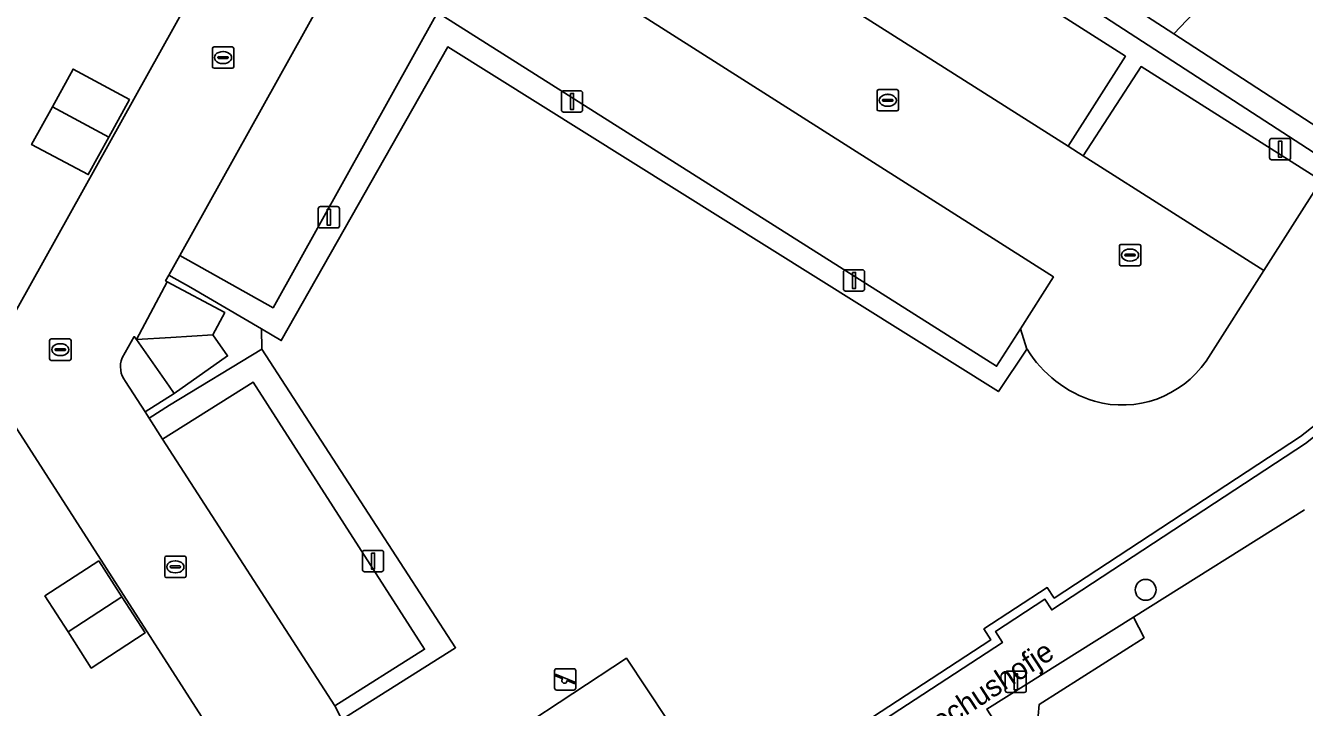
# Model space of a CAD drawing. Extents: x 161798 to 162385, y 382315 to 382833.
# Drawn here: x 162038.7 to 162098.6, y 382627.8 to 382659.8 of the extents above; entities that cross this region are included whole.
import ezdxf

# ---------------------------------------------------------------- set-up
doc = ezdxf.new("R2010")
doc.units = 0
for name, color, linetype in [('IMGEO_Boom', 7, 'Continuous'), ('IMGEO_Erf', 7, 'Continuous'), ('IMGEO_Grasland_overig', 7, 'Continuous'), ('IMGEO_Groenvoorziening', 7, 'Continuous'), ('IMGEO_Haag', 7, 'Continuous'), ('IMGEO_Kolk', 7, 'Continuous'), ('IMGEO_Lichtmast', 7, 'Continuous'), ('IMGEO_Openbare_ruimte_label', 7, 'Continuous'), ('IMGEO_Pand', 7, 'Continuous'), ('IMGEO_Parkeervlak_open', 7, 'Continuous'), ('IMGEO_Rijbaan_lokaal_open', 7, 'Continuous'), ('IMGEO_Speelvoorziening', 7, 'Continuous'), ('IMGEO_Voetpad_halfverhard', 7, 'Continuous'), ('IMGEO_Voetpad_open', 7, 'Continuous')]:
    doc.layers.add(name, color=color, linetype=linetype)

msp = doc.modelspace()

# ---------------------------------------------------------------- linework, layer by layer
at = {"layer": 'IMGEO_Boom'}
msp.add_circle((162091.193, 382633.351), 0.489, dxfattribs=at)
at = {"layer": 'IMGEO_Erf'}
for points in [[(162037.089, 382644.31), (162054.299, 382675.209)], [(162038.559, 382617.282), (162041.785, 382619.378), (162042.883, 382620.082), (162044.823, 382621.326), (162043.353, 382623.574), (162047.566, 382626.266), (162049.021, 382623.989), (162049.126, 382624.056), (162037.386, 382642.326)], [(162098.642, 382637.101), (162090.621, 382632.077), (162091.121, 382631.109), (162086.211, 382627.989), (162086.065, 382626.396), (162085.935, 382626.314), (162096.136, 382610.823), (162098.869, 382612.622), (162093.624, 382620.587), (162096.461, 382622.456), (162096.703, 382622.616), (162099.695, 382624.586)]]:
    msp.add_lwpolyline(points, dxfattribs=at)
for points in [[(162039.979, 382655.972), (162040.95, 382657.742), (162043.593, 382656.309), (162042.628, 382654.553), (162041.663, 382652.796), (162039.008, 382654.202)], [(162042.153, 382634.71), (162043.237, 382633.023), (162044.321, 382631.337), (162041.799, 382629.691), (162040.715, 382631.378), (162039.631, 382633.064)]]:
    msp.add_lwpolyline(points, close=True, dxfattribs=at)
at = {"layer": 'IMGEO_Grasland_overig'}
for points in [[(162100.721, 382642.321), (162098.453, 382640.526), (162086.912, 382632.968), (162086.587, 382633.461), (162083.617, 382631.522), (162083.938, 382631.006), (162071.632, 382622.978), (162071.854, 382622.645), (162084.484, 382630.885), (162084.164, 382631.401), (162086.472, 382632.908), (162086.798, 382632.415), (162098.687, 382640.201), (162100.953, 382641.994), (162107.365, 382646.048), (162107.093, 382646.349)], [(162049.39, 382643.077), (162057.419, 382630.57), (162053.217, 382627.917), (162053.546, 382627.275), (162058.865, 382630.636), (162049.788, 382644.621), (162045.462, 382642.006), (162044.511, 382641.395), (162045.145, 382640.409)]]:
    msp.add_lwpolyline(points, close=True, dxfattribs=at)
at = {"layer": 'IMGEO_Groenvoorziening'}
for points in [[(162085.636, 382644.628), (162084.298, 382642.637), (162058.5, 382658.78), (162050.703, 382645.029), (162049.772, 382645.572), (162049.788, 382644.621), (162058.865, 382630.636), (162053.546, 382627.275), (162060.874, 382615.465), (162063.849, 382617.311), (162065.587, 382618.465), (162065.303, 382618.88), (162066.568, 382619.672), (162061.847, 382626.837), (162066.874, 382630.15), (162071.632, 382622.978), (162083.938, 382631.006), (162083.617, 382631.522), (162086.587, 382633.461), (162086.912, 382632.968), (162098.453, 382640.526)], [(162098.453, 382640.526), (162100.721, 382642.321), (162107.093, 382646.349), (162105.404, 382648.013), (162101.431, 382651.203), (162099.476, 382652.633), (162099.415, 382652.521), (162096.732, 382648.306), (162094.025, 382644.065)]]:
    msp.add_lwpolyline(points, dxfattribs=at)
msp.add_lwpolyline([(162086.211, 382627.989), (162091.121, 382631.109), (162090.621, 382632.077), (162083.747, 382627.769), (162085.049, 382625.755), (162085.935, 382626.314), (162086.065, 382626.396)], close=True, dxfattribs=at)
for centre, radius, start, end in [((162090.469, 382647.611), 5.679, 211.68946, 252.87253), ((162090.091, 382646.793), 4.787, 254.30632, 325.2635)]:
    msp.add_arc(centre, radius, start, end, dxfattribs=at)
at = {"layer": 'IMGEO_Haag'}
msp.add_lwpolyline([(162098.687, 382640.201), (162100.953, 382641.994), (162107.365, 382646.048), (162107.093, 382646.349), (162100.721, 382642.321), (162098.453, 382640.526), (162086.912, 382632.968), (162086.587, 382633.461), (162083.617, 382631.522), (162083.938, 382631.006), (162071.632, 382622.978), (162071.854, 382622.645), (162084.484, 382630.885), (162084.164, 382631.401), (162086.472, 382632.908), (162086.798, 382632.415)], close=True, dxfattribs=at)
at = {"layer": 'IMGEO_Kolk'}
for p, q in [((162047.477, 382657.853), (162047.477, 382658.705)), ((162047.552, 382658.779), (162048.404, 382658.779)), ((162047.965, 382658.559), (162047.99, 382658.559)), ((162048.478, 382658.705), (162048.478, 382657.853)), ((162048.404, 382657.779), (162047.552, 382657.779)), ((162047.736, 382658.273), (162047.736, 382658.285)), ((162048.174, 382658.236), (162047.776, 382658.236)), ((162047.779, 382658.322), (162048.177, 382658.322)), ((162047.988, 382657.999), (162047.963, 382657.999)), ((162048.22, 382658.285), (162048.22, 382658.273)), ((162078.614, 382655.852), (162078.614, 382656.704)), ((162078.689, 382656.778), (162079.541, 382656.778)), ((162079.615, 382656.704), (162079.615, 382655.852)), ((162078.873, 382656.272), (162078.873, 382656.284)), ((162079.311, 382656.235), (162078.913, 382656.235)), ((162078.916, 382656.321), (162079.314, 382656.321)), ((162079.125, 382655.998), (162079.1, 382655.998)), ((162079.102, 382656.558), (162079.127, 382656.558)), ((162079.357, 382656.284), (162079.357, 382656.272)), ((162079.541, 382655.778), (162078.689, 382655.778)), ((162089.964, 382648.604), (162089.964, 382649.456)), ((162090.039, 382649.53), (162090.891, 382649.53)), ((162090.965, 382649.456), (162090.965, 382648.604)), ((162090.223, 382649.024), (162090.223, 382649.036)), ((162090.661, 382648.987), (162090.263, 382648.987)), ((162090.266, 382649.073), (162090.664, 382649.073)), ((162090.452, 382649.31), (162090.477, 382649.31)), ((162090.707, 382649.036), (162090.707, 382649.024)), ((162090.891, 382648.53), (162090.039, 382648.53)), ((162090.475, 382648.75), (162090.45, 382648.75)), ((162039.852, 382644.174), (162039.852, 382645.026)), ((162039.927, 382645.1), (162040.779, 382645.1)), ((162040.111, 382644.594), (162040.111, 382644.606)), ((162040.154, 382644.643), (162040.552, 382644.643)), ((162040.34, 382644.88), (162040.365, 382644.88)), ((162040.595, 382644.606), (162040.595, 382644.594)), ((162040.853, 382645.026), (162040.853, 382644.174)), ((162040.779, 382644.1), (162039.927, 382644.1)), ((162040.549, 382644.557), (162040.151, 382644.557)), ((162040.363, 382644.32), (162040.338, 382644.32)), ((162045.243, 382634.002), (162045.243, 382634.854)), ((162045.318, 382634.928), (162046.17, 382634.928)), ((162045.502, 382634.422), (162045.502, 382634.434)), ((162045.545, 382634.471), (162045.943, 382634.471)), ((162045.731, 382634.708), (162045.756, 382634.708)), ((162045.986, 382634.434), (162045.986, 382634.422)), ((162046.244, 382634.854), (162046.244, 382634.002)), ((162046.17, 382633.928), (162045.318, 382633.928)), ((162045.94, 382634.385), (162045.542, 382634.385)), ((162045.754, 382634.148), (162045.729, 382634.148))]:
    msp.add_line(p, q, dxfattribs=at)
for points in [[(162047.477, 382657.853), (162047.477, 382658.705)], [(162047.552, 382658.779), (162048.404, 382658.779)], [(162048.478, 382658.705), (162048.478, 382657.853)], [(162048.404, 382657.779), (162047.552, 382657.779)], [(162078.614, 382655.852), (162078.614, 382656.704)], [(162078.689, 382656.778), (162079.541, 382656.778)], [(162079.615, 382656.704), (162079.615, 382655.852)], [(162079.541, 382655.778), (162078.689, 382655.778)], [(162089.964, 382648.604), (162089.964, 382649.456)], [(162090.039, 382649.53), (162090.891, 382649.53)], [(162090.965, 382649.456), (162090.965, 382648.604)], [(162090.891, 382648.53), (162090.039, 382648.53)], [(162039.852, 382644.174), (162039.852, 382645.026)], [(162039.927, 382645.1), (162040.779, 382645.1)], [(162040.853, 382645.026), (162040.853, 382644.174)], [(162040.779, 382644.1), (162039.927, 382644.1)], [(162045.243, 382634.002), (162045.243, 382634.854)], [(162045.318, 382634.928), (162046.17, 382634.928)], [(162046.244, 382634.854), (162046.244, 382634.002)], [(162046.17, 382633.928), (162045.318, 382633.928)]]:
    msp.add_lwpolyline(points, dxfattribs=at)
for centre, radius, start, end in [((162047.554, 382658.703), 0.0765, 91.55205, 178.44795), ((162047.554, 382658.703), 0.0765, 91.55205, 178.44795), ((162048.402, 382658.703), 0.0765, 1.55205, 88.44795), ((162048.402, 382658.703), 0.0765, 1.55205, 88.44795), ((162047.554, 382657.855), 0.0765, 181.55205, 268.44795), ((162047.554, 382657.855), 0.0765, 181.55205, 268.44795), ((162047.776, 382658.282), 0.0403, 85.87752, 175.75265), ((162047.773, 382658.272), 0.0366, 178.93798, 274.71019), ((162048.177, 382658.279), 0.043, 264.86636, 352.45326), ((162048.181, 382658.284), 0.0386, 1.73085, 96.63898), ((162048.402, 382657.855), 0.0765, 271.55205, 358.44795), ((162048.402, 382657.855), 0.0765, 271.55205, 358.44795), ((162078.691, 382656.702), 0.0765, 91.55205, 178.44795), ((162078.691, 382656.702), 0.0765, 91.55205, 178.44795), ((162079.539, 382656.702), 0.0765, 1.55205, 88.44795), ((162079.539, 382656.702), 0.0765, 1.55205, 88.44795), ((162078.913, 382656.281), 0.0403, 85.87752, 175.75265), ((162078.91, 382656.271), 0.0366, 178.93798, 274.71019), ((162079.314, 382656.278), 0.043, 264.86636, 352.45326), ((162079.318, 382656.283), 0.0386, 1.73085, 96.63898), ((162078.691, 382655.854), 0.0765, 181.55205, 268.44795), ((162078.691, 382655.854), 0.0765, 181.55205, 268.44795), ((162079.539, 382655.854), 0.0765, 271.55205, 358.44795), ((162079.539, 382655.854), 0.0765, 271.55205, 358.44795), ((162090.041, 382649.454), 0.0765, 91.55205, 178.44795), ((162090.041, 382649.454), 0.0765, 91.55205, 178.44795), ((162090.889, 382649.454), 0.0765, 1.55205, 88.44795), ((162090.889, 382649.454), 0.0765, 1.55205, 88.44795), ((162090.263, 382649.033), 0.0403, 85.87752, 175.75265), ((162090.26, 382649.023), 0.0366, 178.93798, 274.71019), ((162090.664, 382649.03), 0.043, 264.86636, 352.45326), ((162090.668, 382649.035), 0.0386, 1.73085, 96.63898), ((162090.041, 382648.606), 0.0765, 181.55205, 268.44795), ((162090.041, 382648.606), 0.0765, 181.55205, 268.44795), ((162090.889, 382648.606), 0.0765, 271.55205, 358.44795), ((162090.889, 382648.606), 0.0765, 271.55205, 358.44795), ((162039.929, 382645.024), 0.0765, 91.55205, 178.44795), ((162039.929, 382645.024), 0.0765, 91.55205, 178.44795), ((162040.151, 382644.603), 0.0403, 85.87752, 175.75265), ((162040.148, 382644.593), 0.0366, 178.93798, 274.71019), ((162040.552, 382644.6), 0.043, 264.86636, 352.45326), ((162040.556, 382644.605), 0.0386, 1.73085, 96.63898), ((162040.777, 382645.024), 0.0765, 1.55205, 88.44795), ((162040.777, 382645.024), 0.0765, 1.55205, 88.44795), ((162039.929, 382644.176), 0.0765, 181.55205, 268.44795), ((162039.929, 382644.176), 0.0765, 181.55205, 268.44795), ((162040.777, 382644.176), 0.0765, 271.55205, 358.44795), ((162040.777, 382644.176), 0.0765, 271.55205, 358.44795), ((162045.32, 382634.852), 0.0765, 91.55205, 178.44795), ((162045.32, 382634.852), 0.0765, 91.55205, 178.44795), ((162045.542, 382634.431), 0.0403, 85.87752, 175.75265), ((162045.539, 382634.421), 0.0366, 178.93798, 274.71019), ((162045.943, 382634.428), 0.043, 264.86636, 352.45326), ((162045.947, 382634.433), 0.0386, 1.73085, 96.63898), ((162046.168, 382634.852), 0.0765, 1.55205, 88.44795), ((162046.168, 382634.852), 0.0765, 1.55205, 88.44795), ((162045.32, 382634.004), 0.0765, 181.55205, 268.44795), ((162045.32, 382634.004), 0.0765, 181.55205, 268.44795), ((162046.168, 382634.004), 0.0765, 271.55205, 358.44795), ((162046.168, 382634.004), 0.0765, 271.55205, 358.44795)]:
    msp.add_arc(centre, radius, start, end, dxfattribs=at)
for centre, major_axis, ratio, start_param, end_param in [((162047.964, 382658.279), (-0.387, 0.002), 0.722429, 4.712389, 7.853982), ((162047.989, 382658.279), (-0.39, 0.002), 0.717154, 1.570796, 4.712389), ((162079.101, 382656.278), (-0.387, 0.002), 0.722429, 4.712389, 7.853982), ((162079.126, 382656.278), (-0.39, 0.002), 0.717154, 1.570796, 4.712389), ((162090.451, 382649.03), (-0.387, 0.002), 0.722429, 4.712389, 7.853982), ((162090.476, 382649.03), (-0.39, 0.002), 0.717154, 1.570796, 4.712389), ((162040.339, 382644.6), (-0.387, 0.002), 0.722429, 4.712389, 7.853982), ((162040.364, 382644.6), (-0.39, 0.002), 0.717154, 1.570796, 4.712389), ((162045.73, 382634.428), (-0.387, 0.002), 0.722429, 4.712389, 7.853982), ((162045.755, 382634.428), (-0.39, 0.002), 0.717154, 1.570796, 4.712389)]:
    msp.add_ellipse(centre, major_axis=major_axis, ratio=ratio, start_param=start_param, end_param=end_param, dxfattribs=at)
at = {"layer": 'IMGEO_Lichtmast'}
for p, q in [((162063.829, 382655.827), (162063.829, 382656.627)), ((162063.829, 382656.627), (162063.829, 382655.827)), ((162063.929, 382656.727), (162064.719, 382656.727)), ((162064.719, 382656.727), (162063.929, 382656.727)), ((162064.819, 382656.627), (162064.819, 382655.827)), ((162064.819, 382655.827), (162064.819, 382656.627)), ((162064.719, 382655.727), (162063.929, 382655.727)), ((162063.929, 382655.727), (162064.719, 382655.727)), ((162096.997, 382653.591), (162096.997, 382654.391)), ((162096.997, 382654.391), (162096.997, 382653.591)), ((162097.097, 382654.491), (162097.887, 382654.491)), ((162097.887, 382654.491), (162097.097, 382654.491)), ((162097.987, 382654.391), (162097.987, 382653.591)), ((162097.987, 382653.591), (162097.987, 382654.391)), ((162097.887, 382653.491), (162097.097, 382653.491)), ((162097.097, 382653.491), (162097.887, 382653.491)), ((162052.435, 382650.399), (162052.435, 382651.199)), ((162052.435, 382651.199), (162052.435, 382650.399)), ((162052.535, 382651.299), (162053.325, 382651.299)), ((162053.325, 382651.299), (162052.535, 382651.299)), ((162053.425, 382651.199), (162053.425, 382650.399)), ((162053.425, 382650.399), (162053.425, 382651.199)), ((162053.325, 382650.299), (162052.535, 382650.299)), ((162052.535, 382650.299), (162053.325, 382650.299)), ((162077.037, 382647.444), (162077.037, 382648.244)), ((162077.037, 382648.244), (162077.037, 382647.444)), ((162077.137, 382648.344), (162077.927, 382648.344)), ((162077.927, 382648.344), (162077.137, 382648.344)), ((162078.027, 382648.244), (162078.027, 382647.444)), ((162078.027, 382647.444), (162078.027, 382648.244)), ((162077.927, 382647.344), (162077.137, 382647.344)), ((162077.137, 382647.344), (162077.927, 382647.344)), ((162054.504, 382634.301), (162054.504, 382635.101)), ((162054.504, 382635.101), (162054.504, 382634.301)), ((162054.604, 382635.201), (162055.394, 382635.201)), ((162055.394, 382635.201), (162054.604, 382635.201)), ((162055.494, 382635.101), (162055.494, 382634.301)), ((162055.494, 382634.301), (162055.494, 382635.101)), ((162055.394, 382634.201), (162054.604, 382634.201)), ((162054.604, 382634.201), (162055.394, 382634.201)), ((162084.615, 382628.645), (162084.615, 382629.445)), ((162084.615, 382629.445), (162084.615, 382628.645)), ((162084.715, 382629.545), (162085.505, 382629.545)), ((162085.505, 382629.545), (162084.715, 382629.545)), ((162085.605, 382629.445), (162085.605, 382628.645)), ((162085.605, 382628.645), (162085.605, 382629.445)), ((162085.505, 382628.545), (162084.715, 382628.545)), ((162084.715, 382628.545), (162085.505, 382628.545))]:
    msp.add_line(p, q, dxfattribs=at)
for points in [[(162064.249, 382656.602), (162064.399, 382656.602), (162064.399, 382655.852), (162064.249, 382655.852), (162064.249, 382656.602)], [(162097.417, 382654.366), (162097.567, 382654.366), (162097.567, 382653.616), (162097.417, 382653.616), (162097.417, 382654.366)], [(162052.855, 382651.174), (162053.005, 382651.174), (162053.005, 382650.424), (162052.855, 382650.424), (162052.855, 382651.174)], [(162077.457, 382648.219), (162077.607, 382648.219), (162077.607, 382647.469), (162077.457, 382647.469), (162077.457, 382648.219)], [(162054.924, 382635.076), (162055.074, 382635.076), (162055.074, 382634.326), (162054.924, 382634.326), (162054.924, 382635.076)], [(162085.035, 382629.42), (162085.185, 382629.42), (162085.185, 382628.67), (162085.035, 382628.67), (162085.035, 382629.42)]]:
    msp.add_lwpolyline(points, dxfattribs=at)
for centre, start, end in [((162063.929, 382656.627), 90, 180), ((162063.929, 382656.627), 90, 180), ((162064.719, 382656.627), 0, 90), ((162064.719, 382656.627), 360, 90), ((162063.929, 382655.827), 180, 270), ((162063.929, 382655.827), 180, 270), ((162064.719, 382655.827), 270, 0), ((162064.719, 382655.827), 270, 0), ((162097.097, 382654.391), 90, 180), ((162097.097, 382654.391), 90, 180), ((162097.887, 382654.391), 0, 90), ((162097.887, 382654.391), 360, 90), ((162097.097, 382653.591), 180, 270), ((162097.097, 382653.591), 180, 270), ((162097.887, 382653.591), 270, 0), ((162097.887, 382653.591), 270, 0), ((162052.535, 382651.199), 90, 180), ((162052.535, 382651.199), 90, 180), ((162053.325, 382651.199), 0, 90), ((162053.325, 382651.199), 360, 90), ((162052.535, 382650.399), 180, 270), ((162052.535, 382650.399), 180, 270), ((162053.325, 382650.399), 270, 0), ((162053.325, 382650.399), 270, 0), ((162077.137, 382648.244), 90, 180), ((162077.137, 382648.244), 90, 180), ((162077.927, 382648.244), 0, 90), ((162077.927, 382648.244), 360, 90), ((162077.137, 382647.444), 180, 270), ((162077.137, 382647.444), 180, 270), ((162077.927, 382647.444), 270, 0), ((162077.927, 382647.444), 270, 0), ((162054.604, 382635.101), 90, 180), ((162054.604, 382635.101), 90, 180), ((162055.394, 382635.101), 0, 90), ((162055.394, 382635.101), 360, 90), ((162054.604, 382634.301), 180, 270), ((162054.604, 382634.301), 180, 270), ((162055.394, 382634.301), 270, 0), ((162055.394, 382634.301), 270, 0), ((162084.715, 382629.445), 90, 180), ((162084.715, 382629.445), 90, 180), ((162085.505, 382629.445), 0, 90), ((162085.505, 382629.445), 360, 90), ((162084.715, 382628.645), 180, 270), ((162084.715, 382628.645), 180, 270), ((162085.505, 382628.645), 270, 0), ((162085.505, 382628.645), 270, 0)]:
    msp.add_arc(centre, 0.1, start, end, dxfattribs=at)
at = {"layer": 'IMGEO_Pand'}
for points in [[(162106.594, 382675.618), (162104.136, 382677.116), (162103.949, 382677.238), (162087.494, 382688.013), (162080.055, 382677.948), (162078.981, 382678.576), (162074.525, 382674.387), (162072.358, 382671.028), (162072.648, 382670.851), (162072.703, 382670.936), (162073.412, 382672.036), (162074.251, 382671.491), (162074.142, 382671.323), (162090.218, 382660.88), (162092.518, 382659.386), (162094.953, 382661.964), (162096.171, 382663.253), (162097.075, 382664.32), (162097.929, 382665.328), (162098.773, 382666.323)], [(162039.979, 382655.972), (162042.628, 382654.553), (162043.593, 382656.309), (162040.95, 382657.742)], [(162042.628, 382654.553), (162039.979, 382655.972), (162039.008, 382654.202), (162041.663, 382652.796)], [(162045.358, 382647.784), (162043.915, 382645.073), (162045.529, 382645.172), (162047.502, 382645.293), (162048.057, 382646.336)], [(162047.502, 382645.293), (162045.529, 382645.172), (162043.915, 382645.073), (162045.444, 382642.888), (162045.678, 382642.553), (162048.188, 382644.31)], [(162042.153, 382634.71), (162039.631, 382633.064), (162040.715, 382631.378), (162043.237, 382633.023)], [(162043.237, 382633.023), (162040.715, 382631.378), (162041.799, 382629.691), (162044.321, 382631.337)]]:
    msp.add_lwpolyline(points, close=True, dxfattribs=at)
msp.add_lwpolyline([(162094.953, 382661.964), (162092.518, 382659.386), (162106.053, 382650.594), (162106.401, 382650.789), (162106.885, 382649.914), (162105.935, 382649.39), (162106.092, 382649.106), (162106.192, 382649.16), (162113.749, 382653.246), (162113.889, 382653.134), (162121.881, 382662.313)], dxfattribs=at)
at = {"layer": 'IMGEO_Parkeervlak_open'}
for points in [[(162085.335, 382645.581), (162086.876, 382648.006), (162060.601, 382664.717), (162060.21, 382664.005), (162055.713, 382666.546), (162045.947, 382649.007), (162050.322, 382646.559), (162058.029, 382660.392), (162084.208, 382643.821)], [(162076.445, 382661.19), (162087.562, 382654.137), (162090.247, 382658.342), (162079.125, 382665.431)], [(162099.415, 382652.521), (162090.982, 382657.86), (162088.266, 382653.675), (162096.732, 382648.306)], [(162045.145, 382640.409), (162053.217, 382627.917), (162057.419, 382630.57), (162049.39, 382643.077)]]:
    msp.add_lwpolyline(points, close=True, dxfattribs=at)
at = {"layer": 'IMGEO_Rijbaan_lokaal_open'}
for points in [[(162094.025, 382644.065), (162096.732, 382648.306), (162088.266, 382653.675), (162087.562, 382654.137), (162076.445, 382661.19), (162075.75, 382661.625), (162065.37, 382668.189), (162064.691, 382668.651), (162054.299, 382675.209), (162037.089, 382644.31), (162037.04, 382644.222)], [(162057.065, 382666.906), (162060.601, 382664.717), (162086.876, 382648.006), (162085.335, 382645.581), (162085.636, 382644.628)], [(162043.256, 382644.219), (162043.816, 382645.215), (162043.915, 382645.073), (162045.358, 382647.784), (162045.283, 382647.826), (162045.429, 382648.086), (162045.947, 382649.007), (162055.713, 382666.546)], [(162036.992, 382643.55), (162037.221, 382642.838), (162037.386, 382642.326), (162049.126, 382624.056), (162049.733, 382623.111)], [(162045.145, 382640.409), (162044.511, 382641.395), (162044.326, 382641.685), (162043.407, 382643.115)], [(162053.546, 382627.275), (162053.217, 382627.917), (162045.145, 382640.409)]]:
    msp.add_lwpolyline(points, dxfattribs=at)
for centre, radius, start, end in [((162090.469, 382647.611), 5.679, 211.68946, 252.87253), ((162044.261, 382643.794), 1.091, 157.0865, 218.49015), ((162090.091, 382646.793), 4.787, 254.30632, 325.2635)]:
    msp.add_arc(centre, radius, start, end, dxfattribs=at)
at = {"layer": 'IMGEO_Speelvoorziening'}
for p, q in [((162063.608, 382629.659), (162064.398, 382629.659)), ((162064.398, 382629.659), (162063.608, 382629.659)), ((162063.508, 382628.759), (162063.508, 382629.559)), ((162063.508, 382629.559), (162063.508, 382628.759)), ((162063.891, 382629.187), (162063.552, 382629.324)), ((162063.577, 382629.384), (162064.453, 382629.031)), ((162064.429, 382628.971), (162064.089, 382629.108)), ((162064.498, 382629.559), (162064.498, 382628.759)), ((162064.498, 382628.759), (162064.498, 382629.559)), ((162064.398, 382628.659), (162063.608, 382628.659)), ((162063.608, 382628.659), (162064.398, 382628.659))]:
    msp.add_line(p, q, dxfattribs=at)
for centre, radius, start, end in [((162063.608, 382629.559), 0.1, 90, 180), ((162063.608, 382629.559), 0.1, 90, 180), ((162064.398, 382629.559), 0.1, 0, 90), ((162064.398, 382629.559), 0.1, 360, 90), ((162063.565, 382629.354), 0.0327, 68.07798, 248.07798), ((162063.97, 382629.097), 0.12, 130.99278, 5.16318), ((162064.441, 382629.001), 0.0327, 248.07798, 68.07798), ((162063.608, 382628.759), 0.1, 180, 270), ((162063.608, 382628.759), 0.1, 180, 270), ((162064.398, 382628.759), 0.1, 270, 0), ((162064.398, 382628.759), 0.1, 270, 0)]:
    msp.add_arc(centre, radius, start, end, dxfattribs=at)
at = {"layer": 'IMGEO_Voetpad_halfverhard'}
msp.add_lwpolyline([(162049.772, 382645.572), (162046.464, 382647.504), (162045.429, 382648.086), (162045.283, 382647.826), (162045.358, 382647.784), (162048.057, 382646.336), (162047.502, 382645.293), (162048.188, 382644.31), (162045.678, 382642.553), (162044.326, 382641.685), (162044.511, 382641.395), (162045.462, 382642.006), (162049.788, 382644.621)], close=True, dxfattribs=at)
at = {"layer": 'IMGEO_Voetpad_open'}
for points in [[(162106.885, 382649.914), (162106.401, 382650.789), (162106.053, 382650.594), (162092.518, 382659.386), (162090.218, 382660.88), (162074.142, 382671.323), (162074.251, 382671.491), (162073.412, 382672.036), (162072.703, 382670.936), (162105.935, 382649.39)], [(162058.029, 382660.392), (162050.322, 382646.559), (162045.947, 382649.007), (162045.429, 382648.086), (162046.464, 382647.504), (162049.772, 382645.572), (162050.703, 382645.029), (162058.5, 382658.78), (162084.298, 382642.637), (162085.636, 382644.628), (162085.335, 382645.581), (162084.208, 382643.821)], [(162066.874, 382630.15), (162061.847, 382626.837), (162066.568, 382619.672), (162071.632, 382622.978)]]:
    msp.add_lwpolyline(points, close=True, dxfattribs=at)
for points in [[(162123.146, 382661.769), (162112.73, 382649.402), (162107.896, 382646.361), (162107.688, 382646.703), (162106.192, 382649.16), (162106.092, 382649.106), (162105.935, 382649.39), (162072.703, 382670.936)], [(162079.125, 382665.431), (162090.247, 382658.342), (162087.562, 382654.137), (162088.266, 382653.675), (162090.982, 382657.86), (162099.415, 382652.521)], [(162043.915, 382645.073), (162043.816, 382645.215), (162043.256, 382644.219)], [(162043.407, 382643.115), (162044.326, 382641.685), (162045.678, 382642.553), (162045.444, 382642.888), (162043.915, 382645.073)], [(162098.687, 382640.201), (162086.798, 382632.415), (162086.472, 382632.908), (162084.164, 382631.401), (162084.484, 382630.885), (162071.854, 382622.645)], [(162083.747, 382627.769), (162090.621, 382632.077), (162098.642, 382637.101)]]:
    msp.add_lwpolyline(points, dxfattribs=at)
msp.add_arc((162044.261, 382643.794), 1.091, 157.0865, 218.49015, dxfattribs=at)

# ---------------------------------------------------------------- texts
at = {"layer": 'IMGEO_Openbare_ruimte_label'}
msp.add_text('St Rochushofje', height=1, rotation=33.21354, dxfattribs=at).set_placement((162079.406, 382625.24))

doc.saveas('drawing.dxf')
